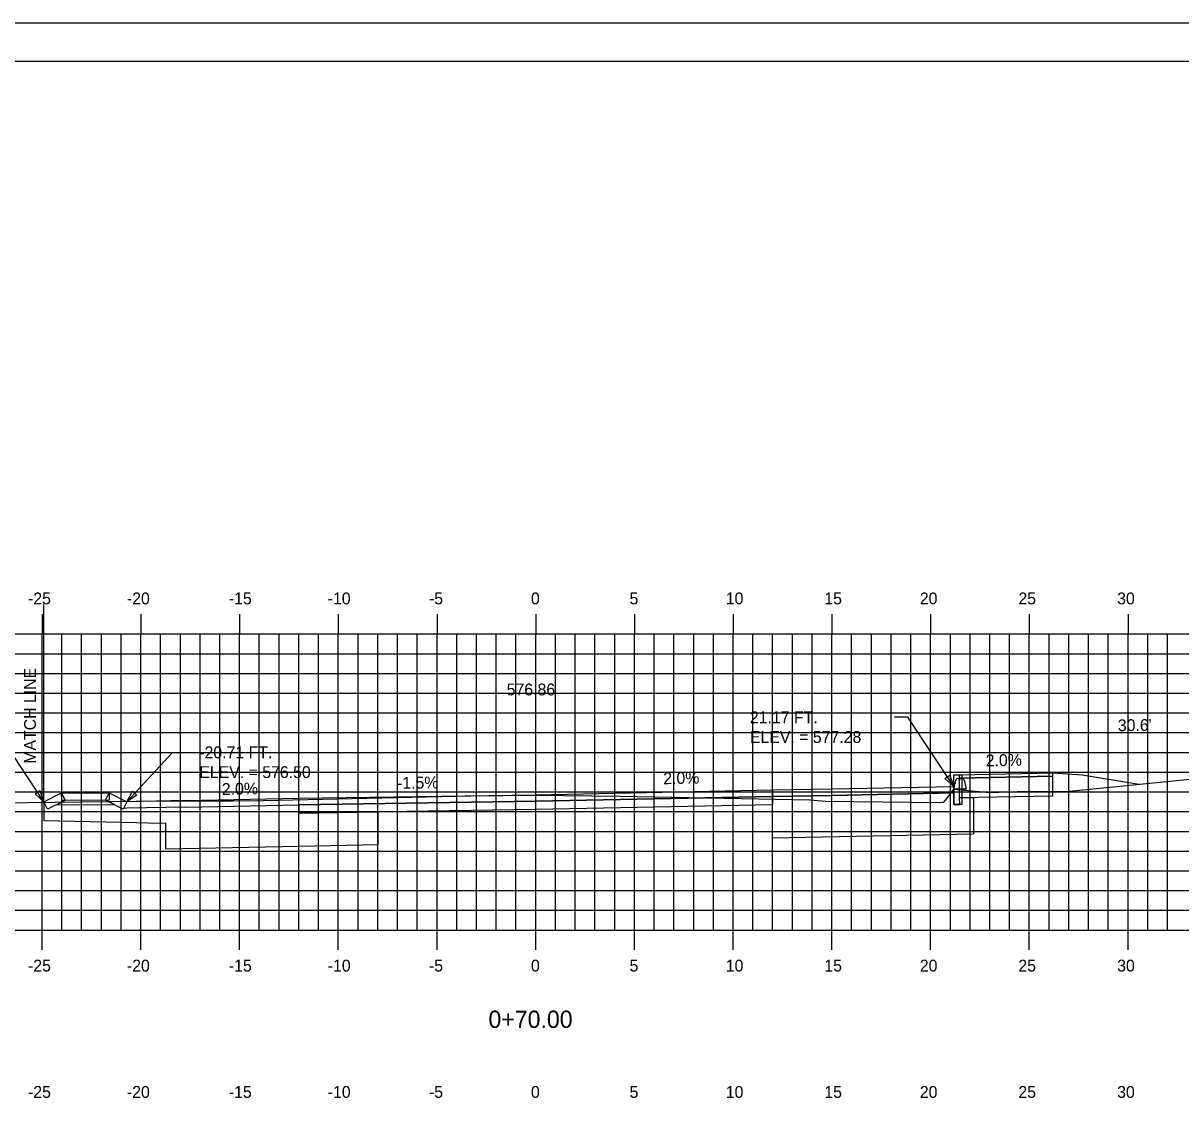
# Model space of a CAD drawing. Extents: x 1048343 to 1048513, y 781387 to 781497.
# Drawn here: x 1048400.2 to 1048458.8, y 781442.6 to 781497.3 of the extents above; entities that cross this region are included whole.
import ezdxf

# ---------------------------------------------------------------- set-up
doc = ezdxf.new("R2010")
doc.units = 0
for name, color, linetype in [('ANNOTATION', 7, 'Continuous'), ('BORDER', 7, 'Continuous'), ('D_Curb_Type1_Lt', 7, 'Continuous'), ('D_Curb_Type_5_Lt', 7, 'Continuous'), ('D_Curb_Type_5_Rt', 7, 'Continuous'), ('D_Roadway_Berm', 7, 'Continuous'), ('D_Roadway_Centerline', 7, 'Continuous'), ('D_Roadway_Centerline_Text', 7, 'Continuous'), ('D_Roadway_Edge_Shoulder', 7, 'Continuous'), ('D_Roadway_Edge_TW', 7, 'Continuous'), ('D_Roadway_Pavement', 7, 'Continuous'), ('D_Roadway_Sidewalks_Paved', 7, 'Continuous'), ('D_Roadway_SlopeLines', 7, 'Continuous'), ('D_Roadway_SubGrade', 7, 'Continuous'), ('D_Text_Standard', 7, 'Continuous'), ('E_ROW_Line', 7, 'Continuous'), ('H_V ANNOTATION', 7, 'Continuous'), ('MAJOR', 7, 'Continuous'), ('MINOR', 7, 'Continuous'), ('PLOT BOUNDARY', 7, 'Continuous'), ('S_Curb_Type_3', 7, 'Continuous'), ('S_Roadway_Centerline', 7, 'Continuous')]:
    doc.layers.add(name, color=color, linetype=linetype)

msp = doc.modelspace()

# ---------------------------------------------------------------- linework, layer by layer
at = {"layer": 'BORDER'}
msp.add_lwpolyline([(1048351.12, 781390.375), (1048511.12, 781390.375), (1048511.12, 781495.375), (1048351.12, 781495.375)], close=True, dxfattribs=at)
at = {"layer": 'D_Curb_Type1_Lt'}
msp.add_lwpolyline([(1048447.706, 781459.239), (1048447.706, 781457.739), (1048447.289, 781457.739), (1048447.289, 781459.239)], close=True, dxfattribs=at)
at = {"layer": 'D_Curb_Type_5_Lt'}
msp.add_lwpolyline([(1048404.518, 781458.324), (1048405.412, 781457.877), (1048405.226, 781457.504), (1048404.332, 781457.952)], close=True, dxfattribs=at)
at = {"layer": 'D_Curb_Type_5_Rt'}
msp.add_lwpolyline([(1048401.205, 781457.871), (1048402.099, 781458.319), (1048402.286, 781457.946), (1048401.391, 781457.499)], close=True, dxfattribs=at)
at = {"layer": 'D_Roadway_Berm'}
msp.add_lwpolyline([(1048452.29, 781459.332), (1048453.79, 781459.242)], dxfattribs=at)
at = {"layer": 'D_Roadway_Edge_Shoulder'}
for p, q in [((1048408.384, 781457.936), (1048405.412, 781457.877)), ((1048408.384, 781457.936), (1048414.119, 781458.051)), ((1048408.384, 781457.603), (1048414.119, 781457.718)), ((1048405.412, 781457.544), (1048405.244, 781457.54)), ((1048408.384, 781457.603), (1048405.412, 781457.544))]:
    msp.add_line(p, q, dxfattribs=at)
msp.add_lwpolyline([(1048438.119, 781458.471), (1048441.119, 781458.531), (1048447.289, 781458.655), (1048447.289, 781458.321), (1048441.119, 781458.198), (1048438.119, 781458.138)], close=True, dxfattribs=at)
at = {"layer": 'D_Roadway_Edge_TW'}
msp.add_lwpolyline([(1048414.119, 781457.718), (1048414.119, 781458.051), (1048426.119, 781458.231), (1048438.119, 781458.471), (1048438.119, 781458.138), (1048426.119, 781457.898)], close=True, dxfattribs=at)
at = {"layer": 'D_Roadway_Pavement'}
msp.add_lwpolyline([(1048414.119, 781457.301), (1048414.119, 781457.718), (1048426.119, 781457.898), (1048438.119, 781458.138), (1048438.119, 781457.721), (1048426.119, 781457.481)], close=True, dxfattribs=at)
at = {"layer": 'D_Roadway_Sidewalks_Paved'}
for points in [[(1048447.59, 781459.238), (1048452.29, 781459.332), (1048452.29, 781459.165), (1048447.59, 781459.071)], [(1048402.099, 781458.319), (1048404.518, 781458.324), (1048404.519, 781457.952), (1048402.286, 781457.946), (1048402.119, 781457.945)], [(1048401.839, 781457.722), (1048404.779, 781457.728), (1048404.332, 781457.952), (1048402.286, 781457.946)]]:
    msp.add_lwpolyline(points, close=True, dxfattribs=at)
at = {"layer": 'D_Roadway_SlopeLines'}
msp.add_lwpolyline([(1048453.79, 781459.242), (1048456.686, 781458.759)], dxfattribs=at)
at = {"layer": 'D_Roadway_SubGrade'}
for p, q in [((1048406.469, 781456.812), (1048407.384, 781456.794)), ((1048438.119, 781456.055), (1048448.289, 781456.258))]:
    msp.add_line(p, q, dxfattribs=at)
msp.add_lwpolyline([(1048447.59, 781459.071), (1048452.29, 781459.165), (1048452.29, 781458.165), (1048447.59, 781458.071)], close=True, dxfattribs=at)
for points in [[(1048438.119, 781456.055), (1048438.119, 781458.138), (1048438.119, 781458.138), (1048441.119, 781458.198), (1048447.289, 781458.321), (1048447.289, 781457.738), (1048447.599, 781457.738), (1048447.59, 781458.071), (1048448.289, 781458.085), (1048448.289, 781456.258)], [(1048401.205, 781457.871), (1048401.205, 781456.917), (1048405.876, 781456.824), (1048406.469, 781456.812)], [(1048408.384, 781457.603), (1048414.119, 781457.718), (1048414.119, 781457.301), (1048418.119, 781457.361), (1048418.119, 781455.695), (1048414.119, 781455.615), (1048407.384, 781455.48), (1048407.384, 781456.794)]]:
    msp.add_lwpolyline(points, dxfattribs=at)
at = {"layer": 'D_Text_Standard'}
for points in [[(1048447.289, 781458.655), (1048444.972, 781462.155), (1048444.292, 781462.155)], [(1048401.205, 781457.871), (1048398.888, 781461.371), (1048398.208, 781461.371)], [(1048405.412, 781457.877), (1048407.719, 781460.377), (1048408.399, 781460.377)]]:
    msp.add_lwpolyline(points, dxfattribs=at)
for points in [[(1048447.289, 781458.655), (1048446.846, 781459.06), (1048447.089, 781459.22)], [(1048401.205, 781457.871), (1048400.762, 781458.276), (1048401.005, 781458.437)], [(1048405.412, 781457.877), (1048405.7, 781458.404), (1048405.914, 781458.206)]]:
    msp.add_lwpolyline(points, close=True, dxfattribs=at)
at = {"layer": 'E_ROW_Line'}
msp.add_line((1048401.205, 781457.871), (1048401.205, 781467.871), dxfattribs=at)
at = {"layer": 'MAJOR'}
for p, q in [((1048401.119, 781467.377), (1048401.119, 781466.375)), ((1048406.119, 781467.377), (1048406.119, 781466.375)), ((1048411.119, 781467.377), (1048411.119, 781466.375)), ((1048416.119, 781467.377), (1048416.119, 781466.375)), ((1048421.119, 781467.377), (1048421.119, 781466.375)), ((1048426.119, 781467.377), (1048426.119, 781466.375)), ((1048431.119, 781467.377), (1048431.119, 781466.375)), ((1048436.119, 781467.377), (1048436.119, 781466.375)), ((1048441.119, 781467.377), (1048441.119, 781466.375)), ((1048446.119, 781467.377), (1048446.119, 781466.375)), ((1048451.119, 781467.377), (1048451.119, 781466.375)), ((1048456.119, 781467.377), (1048456.119, 781466.375)), ((1048356.119, 781466.375), (1048496.119, 781466.375)), ((1048356.119, 781466.375), (1048496.119, 781466.375)), ((1048401.119, 781451.375), (1048401.119, 781466.375)), ((1048406.119, 781451.375), (1048406.119, 781466.375)), ((1048411.119, 781451.375), (1048411.119, 781466.375)), ((1048416.119, 781451.375), (1048416.119, 781466.375)), ((1048421.119, 781451.375), (1048421.119, 781466.375)), ((1048426.119, 781451.375), (1048426.119, 781466.375)), ((1048431.119, 781451.375), (1048431.119, 781466.375)), ((1048436.119, 781451.375), (1048436.119, 781466.375)), ((1048441.119, 781451.375), (1048441.119, 781466.375)), ((1048446.119, 781451.375), (1048446.119, 781466.375)), ((1048451.119, 781451.375), (1048451.119, 781466.375)), ((1048456.119, 781451.375), (1048456.119, 781466.375)), ((1048356.119, 781461.375), (1048496.119, 781461.375)), ((1048356.119, 781456.375), (1048496.119, 781456.375)), ((1048356.119, 781451.375), (1048496.119, 781451.375)), ((1048356.119, 781451.375), (1048496.119, 781451.375)), ((1048401.119, 781450.373), (1048401.119, 781451.375)), ((1048406.119, 781450.373), (1048406.119, 781451.375)), ((1048411.119, 781450.373), (1048411.119, 781451.375)), ((1048416.119, 781450.373), (1048416.119, 781451.375)), ((1048421.119, 781450.373), (1048421.119, 781451.375)), ((1048426.119, 781450.373), (1048426.119, 781451.375)), ((1048431.119, 781450.373), (1048431.119, 781451.375)), ((1048436.119, 781450.373), (1048436.119, 781451.375)), ((1048441.119, 781450.373), (1048441.119, 781451.375)), ((1048446.119, 781450.373), (1048446.119, 781451.375)), ((1048451.119, 781450.373), (1048451.119, 781451.375)), ((1048456.119, 781450.373), (1048456.119, 781451.375))]:
    msp.add_line(p, q, dxfattribs=at)
at = {"layer": 'MINOR'}
for p, q in [((1048402.119, 781451.375), (1048402.119, 781466.375)), ((1048403.119, 781451.375), (1048403.119, 781466.375)), ((1048404.119, 781451.375), (1048404.119, 781466.375)), ((1048405.119, 781451.375), (1048405.119, 781466.375)), ((1048407.119, 781451.375), (1048407.119, 781466.375)), ((1048408.119, 781451.375), (1048408.119, 781466.375)), ((1048409.119, 781451.375), (1048409.119, 781466.375)), ((1048410.119, 781451.375), (1048410.119, 781466.375)), ((1048412.119, 781451.375), (1048412.119, 781466.375)), ((1048413.119, 781451.375), (1048413.119, 781466.375)), ((1048414.119, 781451.375), (1048414.119, 781466.375)), ((1048415.119, 781451.375), (1048415.119, 781466.375)), ((1048417.119, 781451.375), (1048417.119, 781466.375)), ((1048418.119, 781451.375), (1048418.119, 781466.375)), ((1048419.119, 781451.375), (1048419.119, 781466.375)), ((1048420.119, 781451.375), (1048420.119, 781466.375)), ((1048422.119, 781451.375), (1048422.119, 781466.375)), ((1048423.119, 781451.375), (1048423.119, 781466.375)), ((1048424.119, 781451.375), (1048424.119, 781466.375)), ((1048425.119, 781451.375), (1048425.119, 781466.375)), ((1048427.119, 781451.375), (1048427.119, 781466.375)), ((1048428.119, 781451.375), (1048428.119, 781466.375)), ((1048429.119, 781451.375), (1048429.119, 781466.375)), ((1048430.119, 781451.375), (1048430.119, 781466.375)), ((1048432.119, 781451.375), (1048432.119, 781466.375)), ((1048433.119, 781451.375), (1048433.119, 781466.375)), ((1048434.119, 781451.375), (1048434.119, 781466.375)), ((1048435.119, 781451.375), (1048435.119, 781466.375)), ((1048437.119, 781451.375), (1048437.119, 781466.375)), ((1048438.119, 781451.375), (1048438.119, 781466.375)), ((1048439.119, 781451.375), (1048439.119, 781466.375)), ((1048440.119, 781451.375), (1048440.119, 781466.375)), ((1048442.119, 781451.375), (1048442.119, 781466.375)), ((1048443.119, 781451.375), (1048443.119, 781466.375)), ((1048444.119, 781451.375), (1048444.119, 781466.375)), ((1048445.119, 781451.375), (1048445.119, 781466.375)), ((1048447.119, 781451.375), (1048447.119, 781466.375)), ((1048448.119, 781451.375), (1048448.119, 781466.375)), ((1048449.119, 781451.375), (1048449.119, 781466.375)), ((1048450.119, 781451.375), (1048450.119, 781466.375)), ((1048452.119, 781451.375), (1048452.119, 781466.375)), ((1048453.119, 781451.375), (1048453.119, 781466.375)), ((1048454.119, 781451.375), (1048454.119, 781466.375)), ((1048455.119, 781451.375), (1048455.119, 781466.375)), ((1048457.119, 781451.375), (1048457.119, 781466.375)), ((1048458.119, 781451.375), (1048458.119, 781466.375)), ((1048356.119, 781465.375), (1048496.119, 781465.375)), ((1048356.119, 781464.375), (1048496.119, 781464.375)), ((1048356.119, 781463.375), (1048496.119, 781463.375)), ((1048356.119, 781462.375), (1048496.119, 781462.375)), ((1048356.119, 781460.375), (1048496.119, 781460.375)), ((1048356.119, 781459.375), (1048496.119, 781459.375)), ((1048356.119, 781458.375), (1048496.119, 781458.375)), ((1048356.119, 781457.375), (1048496.119, 781457.375)), ((1048356.119, 781455.375), (1048496.119, 781455.375)), ((1048356.119, 781454.375), (1048496.119, 781454.375)), ((1048356.119, 781453.375), (1048496.119, 781453.375)), ((1048356.119, 781452.375), (1048496.119, 781452.375))]:
    msp.add_line(p, q, dxfattribs=at)
at = {"layer": 'PLOT BOUNDARY'}
msp.add_lwpolyline([(1048343.026, 781387.316), (1048513.026, 781387.316), (1048513.026, 781497.316), (1048343.026, 781497.316)], close=True, dxfattribs=at)
at = {"layer": 'S_Curb_Type_3'}
for points in [[(1048447.817, 781458.961), (1048447.92, 781458.516), (1048447.295, 781458.516), (1048447.397, 781458.961)], [(1048447.519, 781459.057), (1048447.695, 781459.057)]]:
    msp.add_lwpolyline(points, dxfattribs=at)
for centre, start, end in [((1048447.519, 781458.932), 90, 167.00538), ((1048447.695, 781458.932), 12.99462, 90)]:
    msp.add_arc(centre, 0.125, start, end, dxfattribs=at)
at = {"layer": 'S_Roadway_Centerline'}
msp.add_lwpolyline([(1048397.617, 781457.799), (1048407.252, 781457.914), (1048410.787, 781457.925), (1048412.312, 781457.934), (1048422.837, 781458.173), (1048426.11, 781458.211), (1048430.391, 781458.158), (1048440.013, 781457.966), (1048440.791, 781457.908), (1048446.565, 781457.829), (1048446.781, 781457.862), (1048446.936, 781458.038), (1048447.295, 781458.516), (1048449.112, 781458.341), (1048450.511, 781458.395), (1048452.444, 781458.391), (1048453.139, 781458.404), (1048454.186, 781458.504), (1048461.437, 781459.246)], dxfattribs=at)

# ---------------------------------------------------------------- texts
at = {"layer": 'ANNOTATION'}
for s, rotation, p in [("30.6'", 0.7396, (1048455.606, 781461.446)), ('2.0%', 1.14576, (1048448.916, 781459.665)), ('-1.5%', 0.86015, (1048419.097, 781458.526)), ('2.0%', 1.14576, (1048432.583, 781458.761)), ('2.0%', 1.14576, (1048410.227, 781458.217))]:
    msp.add_text(s, height=0.6, rotation=rotation, dxfattribs=at).set_placement(p)
at = {"layer": 'D_Roadway_Centerline'}
for s, p in [('C', (1048426.114, 781458.231)), ('L', (1048426.119, 781458.224))]:
    msp.add_text(s, height=0.0146, dxfattribs=at).set_placement(p)
at = {"layer": 'D_Roadway_Centerline_Text'}
msp.add_text('576.86', height=0.6, dxfattribs=at).set_placement((1048424.648, 781463.263))
at = {"layer": 'D_Text_Standard'}
for s, p in [('21.17 FT.', (1048436.966, 781461.855)), ('ELEV. = 577.28', (1048436.966, 781460.855)), ('-20.71 FT.', (1048409.079, 781460.077)), ('ELEV. = 576.50', (1048409.079, 781459.077))]:
    msp.add_text(s, height=0.6, dxfattribs=at).set_placement(p)
at = {"layer": 'E_ROW_Line'}
msp.add_text('MATCH LINE', height=0.6, rotation=90, dxfattribs=at).set_placement((1048400.805, 781459.799))
at = {"layer": 'H_V ANNOTATION'}
for s, height, p in [('-25', 0.6, (1048400.405, 781467.875)), ('-20', 0.6, (1048405.413, 781467.875)), ('-15', 0.6, (1048410.576, 781467.875)), ('-10', 0.6, (1048415.584, 781467.875)), ('-5', 0.6, (1048420.71, 781467.875)), ('0', 0.6, (1048425.878, 781467.875)), ('5', 0.6, (1048430.87, 781467.875)), ('10', 0.6, (1048435.745, 781467.875)), ('15', 0.6, (1048440.737, 781467.875)), ('20', 0.6, (1048445.573, 781467.875)), ('25', 0.6, (1048450.565, 781467.875)), ('30', 0.6, (1048455.568, 781467.875)), ('-25', 0.6, (1048400.405, 781449.275)), ('-20', 0.6, (1048405.413, 781449.275)), ('-15', 0.6, (1048410.576, 781449.275)), ('-10', 0.6, (1048415.584, 781449.275)), ('-5', 0.6, (1048420.71, 781449.275)), ('0', 0.6, (1048425.878, 781449.275)), ('5', 0.6, (1048430.87, 781449.275)), ('10', 0.6, (1048435.745, 781449.275)), ('15', 0.6, (1048440.737, 781449.275)), ('20', 0.6, (1048445.573, 781449.275)), ('25', 0.6, (1048450.565, 781449.275)), ('30', 0.6, (1048455.568, 781449.275)), ('0+70.00', 0.875, (1048423.724, 781446.419)), ('-25', 0.6, (1048400.405, 781442.875)), ('-20', 0.6, (1048405.413, 781442.875)), ('-15', 0.6, (1048410.576, 781442.875)), ('-10', 0.6, (1048415.584, 781442.875)), ('-5', 0.6, (1048420.71, 781442.875)), ('0', 0.6, (1048425.878, 781442.875)), ('5', 0.6, (1048430.87, 781442.875)), ('10', 0.6, (1048435.745, 781442.875)), ('15', 0.6, (1048440.737, 781442.875)), ('20', 0.6, (1048445.573, 781442.875)), ('25', 0.6, (1048450.565, 781442.875)), ('30', 0.6, (1048455.568, 781442.875))]:
    msp.add_text(s, height=height, dxfattribs=at).set_placement(p)
at = {"layer": 'S_Roadway_Centerline'}
for s, p in [('L', (1048426.102, 781458.204)), ('C', (1048426.105, 781458.211))]:
    msp.add_text(s, height=0.0146, dxfattribs=at).set_placement(p)

doc.saveas('drawing.dxf')
